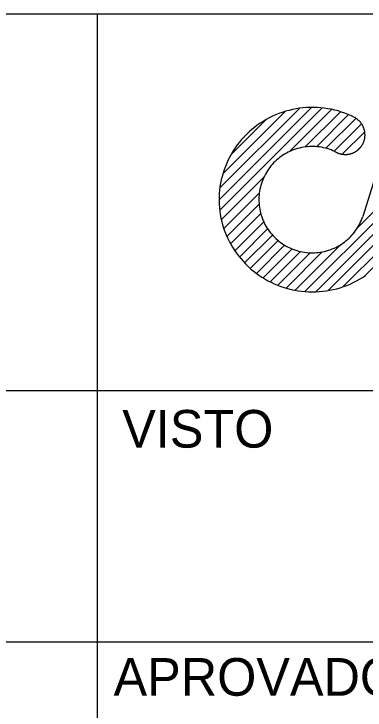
# Model space of a CAD drawing. Extents: x 563 to 3226, y 358 to 960.
# Drawn here: x 2091.57 to 2105.55, y 385.23 to 412.96 of the extents above; entities that cross this region are included whole.
import ezdxf

# ---------------------------------------------------------------- set-up
doc = ezdxf.new("R2010")
doc.units = 0
doc.layers.add('New Level (0)', color=7, linetype='Continuous')

msp = doc.modelspace()

# ---------------------------------------------------------------- linework, layer by layer
at = {"layer": 'New Level (0)'}
for p, q in [((1483.881, 412.956), (2304.881, 412.956)), ((2094.881, 412.956), (2094.881, 367.956)), ((2099.737, 405.558), (2103.412, 409.232)), ((2099.762, 405.14), (2103.835, 409.213)), ((2099.768, 406.03), (2102.934, 409.196)), ((2102.8, 409.175), (2102.661, 409.148)), ((2102.939, 409.197), (2102.8, 409.175)), ((2103.079, 409.214), (2102.939, 409.197)), ((2103.22, 409.225), (2103.079, 409.214)), ((2103.361, 409.232), (2103.22, 409.225)), ((2103.502, 409.233), (2103.361, 409.232)), ((2103.643, 409.228), (2103.502, 409.233)), ((2103.784, 409.218), (2103.643, 409.228)), ((2103.924, 409.203), (2103.784, 409.218)), ((2104.064, 409.183), (2103.924, 409.203)), ((2104.202, 409.158), (2104.064, 409.183)), ((2099.887, 406.591), (2102.368, 409.072)), ((2101.99, 408.936), (2101.861, 408.878)), ((2102.121, 408.988), (2101.99, 408.936)), ((2102.253, 409.036), (2102.121, 408.988)), ((2102.388, 409.078), (2102.253, 409.036)), ((2102.524, 409.116), (2102.388, 409.078)), ((2102.661, 409.148), (2102.524, 409.116)), ((2102.535, 407.472), (2104.218, 409.154)), ((2103.163, 407.657), (2104.569, 409.063)), ((2103.617, 407.669), (2104.893, 408.946)), ((2104.34, 409.127), (2104.202, 409.158)), ((2104.476, 409.091), (2104.34, 409.127)), ((2104.611, 409.05), (2104.476, 409.091)), ((2104.745, 409.005), (2104.611, 409.05)), ((2104.876, 408.954), (2104.745, 409.005)), ((2105.005, 408.898), (2104.876, 408.954)), ((2105.133, 408.838), (2105.005, 408.898)), ((2100.215, 407.361), (2101.593, 408.739)), ((2101.49, 408.678), (2101.372, 408.602)), ((2101.611, 408.749), (2101.49, 408.678)), ((2101.735, 408.816), (2101.611, 408.749)), ((2101.861, 408.878), (2101.735, 408.816)), ((2103.994, 407.604), (2105.19, 408.801)), ((2105.133, 408.836), (2105.115, 408.846)), ((2105.15, 408.826), (2105.133, 408.836)), ((2105.167, 408.816), (2105.15, 408.826)), ((2105.184, 408.805), (2105.167, 408.816)), ((2105.201, 408.794), (2105.184, 408.805)), ((2105.217, 408.782), (2105.201, 408.794)), ((2105.233, 408.77), (2105.217, 408.782)), ((2105.249, 408.757), (2105.233, 408.77)), ((2105.264, 408.745), (2105.249, 408.757)), ((2105.279, 408.731), (2105.264, 408.745)), ((2105.294, 408.718), (2105.279, 408.731)), ((2105.309, 408.704), (2105.294, 408.718)), ((2105.323, 408.69), (2105.309, 408.704)), ((2105.336, 408.675), (2105.323, 408.69)), ((2105.35, 408.66), (2105.336, 408.675)), ((2105.363, 408.645), (2105.35, 408.66)), ((2105.375, 408.629), (2105.363, 408.645)), ((2105.387, 408.613), (2105.375, 408.629)), ((2105.399, 408.597), (2105.387, 408.613)), ((2101.035, 408.349), (2100.93, 408.256)), ((2101.144, 408.437), (2101.035, 408.349)), ((2101.256, 408.522), (2101.144, 408.437)), ((2101.372, 408.602), (2101.256, 408.522)), ((2104.32, 407.489), (2105.411, 408.579)), ((2105.41, 408.58), (2105.399, 408.597)), ((2105.421, 408.564), (2105.41, 408.58)), ((2105.432, 408.547), (2105.421, 408.564)), ((2105.442, 408.53), (2105.432, 408.547)), ((2105.452, 408.512), (2105.442, 408.53)), ((2105.461, 408.494), (2105.452, 408.512)), ((2105.47, 408.476), (2105.461, 408.494)), ((2106.557, 408.426), (2105.461, 404.892)), ((2105.478, 408.458), (2105.47, 408.476)), ((2105.486, 408.44), (2105.478, 408.458)), ((2105.493, 408.422), (2105.486, 408.44)), ((2105.5, 408.403), (2105.493, 408.422)), ((2105.507, 408.384), (2105.5, 408.403)), ((2105.513, 408.365), (2105.507, 408.384)), ((2105.518, 408.346), (2105.513, 408.365)), ((2105.524, 408.327), (2105.518, 408.346)), ((2100.73, 408.059), (2100.636, 407.955)), ((2100.828, 408.159), (2100.73, 408.059)), ((2100.93, 408.256), (2100.828, 408.159)), ((2104.643, 407.37), (2105.537, 408.263)), ((2105.528, 408.308), (2105.524, 408.327)), ((2105.532, 408.288), (2105.528, 408.308)), ((2105.536, 408.269), (2105.532, 408.288)), ((2105.539, 408.249), (2105.536, 408.269)), ((2105.542, 408.23), (2105.539, 408.249)), ((2105.544, 408.21), (2105.542, 408.23)), ((2105.543, 408.052), (2105.545, 408.072)), ((2105.545, 408.19), (2105.544, 408.21)), ((2105.546, 408.17), (2105.545, 408.19)), ((2105.545, 408.072), (2105.546, 408.091)), ((2105.547, 408.15), (2105.546, 408.17)), ((2105.546, 408.091), (2105.547, 408.111)), ((2105.547, 408.131), (2105.547, 408.15)), ((2105.547, 408.111), (2105.547, 408.131)), ((2100.546, 407.848), (2100.46, 407.737)), ((2100.636, 407.955), (2100.546, 407.848)), ((2105.457, 407.772), (2105.466, 407.789)), ((2105.466, 407.789), (2105.474, 407.807)), ((2105.474, 407.807), (2105.482, 407.825)), ((2105.482, 407.825), (2105.49, 407.843)), ((2105.49, 407.843), (2105.497, 407.861)), ((2105.497, 407.861), (2105.504, 407.88)), ((2105.504, 407.88), (2105.51, 407.898)), ((2105.51, 407.898), (2105.516, 407.917)), ((2105.516, 407.917), (2105.521, 407.936)), ((2105.521, 407.936), (2105.526, 407.955)), ((2105.526, 407.955), (2105.53, 407.974)), ((2105.53, 407.974), (2105.534, 407.994)), ((2105.534, 407.994), (2105.537, 408.013)), ((2105.537, 408.013), (2105.54, 408.032)), ((2105.54, 408.032), (2105.543, 408.052)), ((2100.302, 407.506), (2100.229, 407.387)), ((2100.379, 407.623), (2100.302, 407.506)), ((2100.46, 407.737), (2100.379, 407.623)), ((2102.632, 407.515), (2102.558, 407.483)), ((2102.706, 407.544), (2102.632, 407.515)), ((2102.782, 407.57), (2102.706, 407.544)), ((2102.858, 407.594), (2102.782, 407.57)), ((2102.936, 407.614), (2102.858, 407.594)), ((2103.014, 407.632), (2102.936, 407.614)), ((2103.093, 407.647), (2103.014, 407.632)), ((2103.172, 407.659), (2103.093, 407.647)), ((2103.251, 407.668), (2103.172, 407.659)), ((2103.331, 407.673), (2103.251, 407.668)), ((2103.411, 407.676), (2103.331, 407.673)), ((2103.492, 407.676), (2103.411, 407.676)), ((2103.572, 407.673), (2103.492, 407.676)), ((2103.652, 407.667), (2103.572, 407.673)), ((2103.731, 407.657), (2103.652, 407.667)), ((2103.81, 407.645), (2103.731, 407.657)), ((2103.889, 407.63), (2103.81, 407.645)), ((2103.967, 407.612), (2103.889, 407.63)), ((2104.044, 407.591), (2103.967, 407.612)), ((2104.121, 407.567), (2104.044, 407.591)), ((2104.196, 407.54), (2104.121, 407.567)), ((2104.271, 407.51), (2104.196, 407.54)), ((2104.344, 407.478), (2104.271, 407.51)), ((2105.209, 407.497), (2105.225, 407.508)), ((2105.22, 407.504), (2105.407, 407.692)), ((2105.225, 407.508), (2105.241, 407.52)), ((2105.241, 407.52), (2105.257, 407.532)), ((2105.257, 407.532), (2105.272, 407.544)), ((2105.272, 407.544), (2105.287, 407.557)), ((2105.287, 407.557), (2105.301, 407.57)), ((2105.301, 407.57), (2105.316, 407.584)), ((2105.316, 407.584), (2105.33, 407.598)), ((2105.33, 407.598), (2105.343, 407.612)), ((2105.343, 407.612), (2105.356, 407.627)), ((2105.356, 407.627), (2105.369, 407.642)), ((2105.369, 407.642), (2105.381, 407.657)), ((2105.381, 407.657), (2105.393, 407.672)), ((2105.393, 407.672), (2105.405, 407.688)), ((2105.405, 407.688), (2105.416, 407.704)), ((2105.416, 407.704), (2105.427, 407.721)), ((2105.427, 407.721), (2105.437, 407.738)), ((2105.437, 407.738), (2105.447, 407.754)), ((2105.447, 407.754), (2105.457, 407.772)), ((2100.162, 407.264), (2100.098, 407.14)), ((2100.229, 407.387), (2100.162, 407.264)), ((2102.148, 407.235), (2102.085, 407.185)), ((2102.212, 407.283), (2102.148, 407.235)), ((2102.278, 407.328), (2102.212, 407.283)), ((2102.346, 407.37), (2102.278, 407.328)), ((2102.415, 407.41), (2102.346, 407.37)), ((2102.486, 407.448), (2102.415, 407.41)), ((2102.558, 407.483), (2102.486, 407.448)), ((2104.341, 407.479), (2104.359, 407.469)), ((2104.359, 407.469), (2104.376, 407.459)), ((2104.376, 407.459), (2104.394, 407.45)), ((2104.394, 407.45), (2104.412, 407.441)), ((2104.412, 407.441), (2104.43, 407.433)), ((2104.43, 407.433), (2104.449, 407.425)), ((2104.449, 407.425), (2104.467, 407.417)), ((2104.467, 407.417), (2104.486, 407.41)), ((2104.486, 407.41), (2104.505, 407.403)), ((2104.505, 407.403), (2104.524, 407.397)), ((2104.524, 407.397), (2104.543, 407.392)), ((2104.543, 407.392), (2104.563, 407.386)), ((2104.563, 407.386), (2104.582, 407.382)), ((2104.582, 407.382), (2104.602, 407.377)), ((2104.602, 407.377), (2104.621, 407.374)), ((2104.621, 407.374), (2104.641, 407.37)), ((2104.641, 407.37), (2104.661, 407.367)), ((2104.661, 407.367), (2104.681, 407.365)), ((2104.681, 407.365), (2104.701, 407.363)), ((2104.701, 407.363), (2104.72, 407.362)), ((2104.72, 407.362), (2104.74, 407.361)), ((2104.74, 407.361), (2104.76, 407.361)), ((2104.76, 407.361), (2104.78, 407.361)), ((2104.78, 407.361), (2104.8, 407.362)), ((2104.8, 407.362), (2104.82, 407.363)), ((2104.82, 407.363), (2104.84, 407.364)), ((2104.84, 407.364), (2104.86, 407.366)), ((2104.86, 407.366), (2104.88, 407.369)), ((2104.88, 407.369), (2104.899, 407.372)), ((2104.899, 407.372), (2104.919, 407.376)), ((2104.919, 407.376), (2104.938, 407.38)), ((2104.938, 407.38), (2104.958, 407.384)), ((2104.958, 407.384), (2104.977, 407.389)), ((2104.977, 407.389), (2104.996, 407.395)), ((2104.996, 407.395), (2105.015, 407.401)), ((2105.015, 407.401), (2105.033, 407.407)), ((2105.033, 407.407), (2105.052, 407.414)), ((2105.052, 407.414), (2105.07, 407.422)), ((2105.07, 407.422), (2105.089, 407.43)), ((2105.089, 407.43), (2105.107, 407.438)), ((2105.107, 407.438), (2105.124, 407.446)), ((2105.124, 407.446), (2105.142, 407.456)), ((2105.142, 407.456), (2105.159, 407.465)), ((2105.159, 407.465), (2105.176, 407.475)), ((2105.176, 407.475), (2105.193, 407.486)), ((2105.193, 407.486), (2105.209, 407.497)), ((2100.04, 407.013), (2099.987, 406.884)), ((2100.098, 407.14), (2100.04, 407.013)), ((2101.856, 406.963), (2101.804, 406.902)), ((2101.91, 407.021), (2101.856, 406.963)), ((2101.966, 407.078), (2101.91, 407.021)), ((2102.025, 407.133), (2101.966, 407.078)), ((2102.085, 407.185), (2102.025, 407.133)), ((2105.247, 404.438), (2107.758, 406.949)), ((2099.939, 406.753), (2099.895, 406.62)), ((2099.987, 406.884), (2099.939, 406.753)), ((2101.662, 406.708), (2101.62, 406.64)), ((2101.707, 406.775), (2101.662, 406.708)), ((2101.754, 406.839), (2101.707, 406.775)), ((2101.804, 406.902), (2101.754, 406.839)), ((2099.857, 406.486), (2099.824, 406.35)), ((2099.827, 404.763), (2101.524, 406.46)), ((2099.895, 406.62), (2099.857, 406.486)), ((2101.509, 406.428), (2101.478, 406.355)), ((2101.543, 406.5), (2101.509, 406.428)), ((2101.58, 406.571), (2101.543, 406.5)), ((2101.62, 406.64), (2101.58, 406.571)), ((2099.796, 406.214), (2099.774, 406.076)), ((2099.824, 406.35), (2099.796, 406.214)), ((2101.4, 406.128), (2101.38, 406.051)), ((2101.423, 406.204), (2101.4, 406.128)), ((2101.449, 406.28), (2101.423, 406.204)), ((2101.478, 406.355), (2101.449, 406.28)), ((2103.152, 401.901), (2107.564, 406.314)), ((2099.757, 405.938), (2099.745, 405.799)), ((2099.774, 406.076), (2099.757, 405.938)), ((2101.349, 405.894), (2101.338, 405.815)), ((2101.363, 405.973), (2101.349, 405.894)), ((2101.38, 406.051), (2101.363, 405.973)), ((2099.739, 405.659), (2099.737, 405.52)), ((2099.745, 405.799), (2099.739, 405.659)), ((2099.922, 404.417), (2101.341, 405.835)), ((2101.324, 405.656), (2101.322, 405.576)), ((2101.322, 405.576), (2101.323, 405.496)), ((2101.329, 405.736), (2101.324, 405.656)), ((2101.338, 405.815), (2101.329, 405.736)), ((2103.584, 401.891), (2107.37, 405.678)), ((2099.737, 405.52), (2099.742, 405.381)), ((2099.742, 405.381), (2099.751, 405.242)), ((2100.045, 404.098), (2101.33, 405.382)), ((2101.323, 405.496), (2101.327, 405.416)), ((2101.327, 405.416), (2101.334, 405.337)), ((2101.334, 405.337), (2101.344, 405.258)), ((2099.751, 405.242), (2099.766, 405.103)), ((2099.766, 405.103), (2099.786, 404.965)), ((2100.192, 403.802), (2101.396, 405.007)), ((2101.344, 405.258), (2101.357, 405.179)), ((2101.357, 405.179), (2101.373, 405.1)), ((2101.373, 405.1), (2101.392, 405.023)), ((2101.392, 405.023), (2101.413, 404.946)), ((2104.076, 401.941), (2107.177, 405.042)), ((2099.786, 404.965), (2099.812, 404.828)), ((2099.812, 404.828), (2099.843, 404.692)), ((2101.413, 404.946), (2101.438, 404.87)), ((2101.438, 404.87), (2101.465, 404.795)), ((2101.465, 404.795), (2101.496, 404.721)), ((2105.374, 404.671), (2105.406, 404.744)), ((2105.406, 404.744), (2105.436, 404.818)), ((2105.436, 404.818), (2105.462, 404.894)), ((2099.843, 404.692), (2099.879, 404.557)), ((2099.879, 404.557), (2099.92, 404.424)), ((2100.359, 403.528), (2101.514, 404.682)), ((2101.496, 404.721), (2101.529, 404.648)), ((2101.529, 404.648), (2101.565, 404.577)), ((2101.565, 404.577), (2101.603, 404.507)), ((2101.603, 404.507), (2101.644, 404.438)), ((2105.218, 404.392), (2105.261, 404.46)), ((2105.261, 404.46), (2105.301, 404.529)), ((2105.301, 404.529), (2105.339, 404.599)), ((2105.339, 404.599), (2105.374, 404.671)), ((2099.92, 404.424), (2099.966, 404.292)), ((2099.966, 404.292), (2100.017, 404.162)), ((2100.547, 403.274), (2101.671, 404.397)), ((2101.644, 404.438), (2101.688, 404.372)), ((2101.688, 404.372), (2101.734, 404.306)), ((2101.734, 404.306), (2101.783, 404.243)), ((2101.783, 404.243), (2101.834, 404.181)), ((2101.834, 404.181), (2101.887, 404.122)), ((2104.666, 402.09), (2106.983, 404.406)), ((2105.022, 404.14), (2105.074, 404.2)), ((2105.074, 404.2), (2105.125, 404.262)), ((2105.125, 404.262), (2105.173, 404.326)), ((2105.173, 404.326), (2105.218, 404.392)), ((2100.017, 404.162), (2100.074, 404.034)), ((2100.074, 404.034), (2100.135, 403.909)), ((2100.135, 403.909), (2100.201, 403.785)), ((2100.754, 403.038), (2101.863, 404.148)), ((2100.979, 402.822), (2102.089, 403.932)), ((2101.887, 404.122), (2101.943, 404.064)), ((2101.943, 404.064), (2102.001, 404.009)), ((2102.001, 404.009), (2102.06, 403.955)), ((2102.06, 403.955), (2102.122, 403.904)), ((2102.122, 403.904), (2102.185, 403.856)), ((2104.727, 403.871), (2104.79, 403.92)), ((2104.79, 403.92), (2104.851, 403.972)), ((2104.851, 403.972), (2104.91, 404.026)), ((2104.91, 404.026), (2104.967, 404.082)), ((2104.967, 404.082), (2105.022, 404.14)), ((2100.201, 403.785), (2100.271, 403.664)), ((2100.271, 403.664), (2100.346, 403.547)), ((2101.223, 402.624), (2102.347, 403.748)), ((2102.185, 403.856), (2102.251, 403.81)), ((2102.251, 403.81), (2102.318, 403.766)), ((2102.318, 403.766), (2102.387, 403.725)), ((2102.387, 403.725), (2102.457, 403.686)), ((2102.457, 403.686), (2102.528, 403.65)), ((2102.528, 403.65), (2102.601, 403.617)), ((2102.762, 401.953), (2104.578, 403.769)), ((2104.24, 403.596), (2104.314, 403.627)), ((2104.314, 403.627), (2104.386, 403.661)), ((2104.386, 403.661), (2104.458, 403.698)), ((2104.458, 403.698), (2104.527, 403.738)), ((2104.527, 403.738), (2104.595, 403.779)), ((2104.595, 403.779), (2104.662, 403.824)), ((2104.662, 403.824), (2104.727, 403.871)), ((2100.346, 403.547), (2100.426, 403.432)), ((2100.426, 403.432), (2100.51, 403.32)), ((2101.487, 402.446), (2102.642, 403.601)), ((2101.771, 402.288), (2102.978, 403.495)), ((2102.076, 402.151), (2103.369, 403.444)), ((2102.406, 402.039), (2103.848, 403.481)), ((2102.601, 403.617), (2102.675, 403.587)), ((2102.675, 403.587), (2102.751, 403.559)), ((2102.751, 403.559), (2102.827, 403.535)), ((2102.827, 403.535), (2102.904, 403.513)), ((2102.904, 403.513), (2102.982, 403.494)), ((2102.982, 403.494), (2103.06, 403.478)), ((2103.06, 403.478), (2103.139, 403.465)), ((2103.139, 403.465), (2103.219, 403.455)), ((2103.219, 403.455), (2103.299, 403.448)), ((2103.299, 403.448), (2103.379, 403.444)), ((2103.379, 403.444), (2103.459, 403.443)), ((2103.459, 403.443), (2103.539, 403.445)), ((2103.539, 403.445), (2103.619, 403.45)), ((2103.619, 403.45), (2103.698, 403.458)), ((2103.698, 403.458), (2103.778, 403.469)), ((2103.778, 403.469), (2103.857, 403.483)), ((2103.857, 403.483), (2103.935, 403.5)), ((2103.935, 403.5), (2104.013, 403.519)), ((2104.013, 403.519), (2104.089, 403.542)), ((2104.089, 403.542), (2104.165, 403.568)), ((2104.165, 403.568), (2104.24, 403.596)), ((2105.54, 402.522), (2106.557, 403.538)), ((2100.51, 403.32), (2100.598, 403.211)), ((2100.598, 403.211), (2100.691, 403.105)), ((2100.691, 403.105), (2100.787, 403.003)), ((2100.787, 403.003), (2100.887, 402.905)), ((2100.887, 402.905), (2100.991, 402.811)), ((2100.991, 402.811), (2101.099, 402.72)), ((2101.099, 402.72), (2101.209, 402.634)), ((2101.209, 402.634), (2101.323, 402.552)), ((2101.323, 402.552), (2101.441, 402.474)), ((2105.45, 402.462), (2105.567, 402.539)), ((2101.441, 402.474), (2101.561, 402.401)), ((2101.561, 402.401), (2101.683, 402.332)), ((2101.683, 402.332), (2101.809, 402.268)), ((2101.809, 402.268), (2101.936, 402.209)), ((2104.952, 402.2), (2105.08, 402.258)), ((2105.08, 402.258), (2105.206, 402.322)), ((2105.206, 402.322), (2105.329, 402.39)), ((2105.329, 402.39), (2105.45, 402.462)), ((2101.936, 402.209), (2102.066, 402.154)), ((2102.066, 402.154), (2102.198, 402.105)), ((2102.198, 402.105), (2102.332, 402.06)), ((2102.332, 402.06), (2102.467, 402.021)), ((2102.467, 402.021), (2102.604, 401.986)), ((2102.604, 401.986), (2102.742, 401.957)), ((2102.742, 401.957), (2102.881, 401.933)), ((2104.145, 401.953), (2104.283, 401.981)), ((2104.283, 401.981), (2104.42, 402.015)), ((2104.42, 402.015), (2104.556, 402.054)), ((2104.556, 402.054), (2104.69, 402.097)), ((2104.69, 402.097), (2104.822, 402.146)), ((2104.822, 402.146), (2104.952, 402.2)), ((2102.881, 401.933), (2103.021, 401.914)), ((2103.021, 401.914), (2103.161, 401.9)), ((2103.161, 401.9), (2103.302, 401.892)), ((2103.302, 401.892), (2103.443, 401.889)), ((2103.443, 401.889), (2103.584, 401.891)), ((2103.584, 401.891), (2103.725, 401.898)), ((2103.725, 401.898), (2103.866, 401.911)), ((2103.866, 401.911), (2104.006, 401.929)), ((2104.006, 401.929), (2104.145, 401.953)), ((2054.881, 397.956), (2236.881, 397.956)), ((2054.881, 387.956), (2134.881, 387.956))]:
    msp.add_line(p, q, dxfattribs=at)

# ---------------------------------------------------------------- texts
for s, p in [('VISTO', (2095.881, 395.685)), ('APROVADO', (2095.537, 385.806))]:
    msp.add_text(s, height=1.5, dxfattribs=at).set_placement(p)

doc.saveas('drawing.dxf')
